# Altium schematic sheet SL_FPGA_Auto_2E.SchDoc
size C; Generated From FPGA Project: SpiritLevel.PRJFPG; UNUSED_SPECIAL: RouteSeparate; UNUSED_IO: Ignore; VREF: Ignore; UNUSED_INPUT: Ignore; DocumentNumber: 1; SheetNumber: 1; SheetTotal: 5; Library Name: SpiritLevel_2E.SchLib
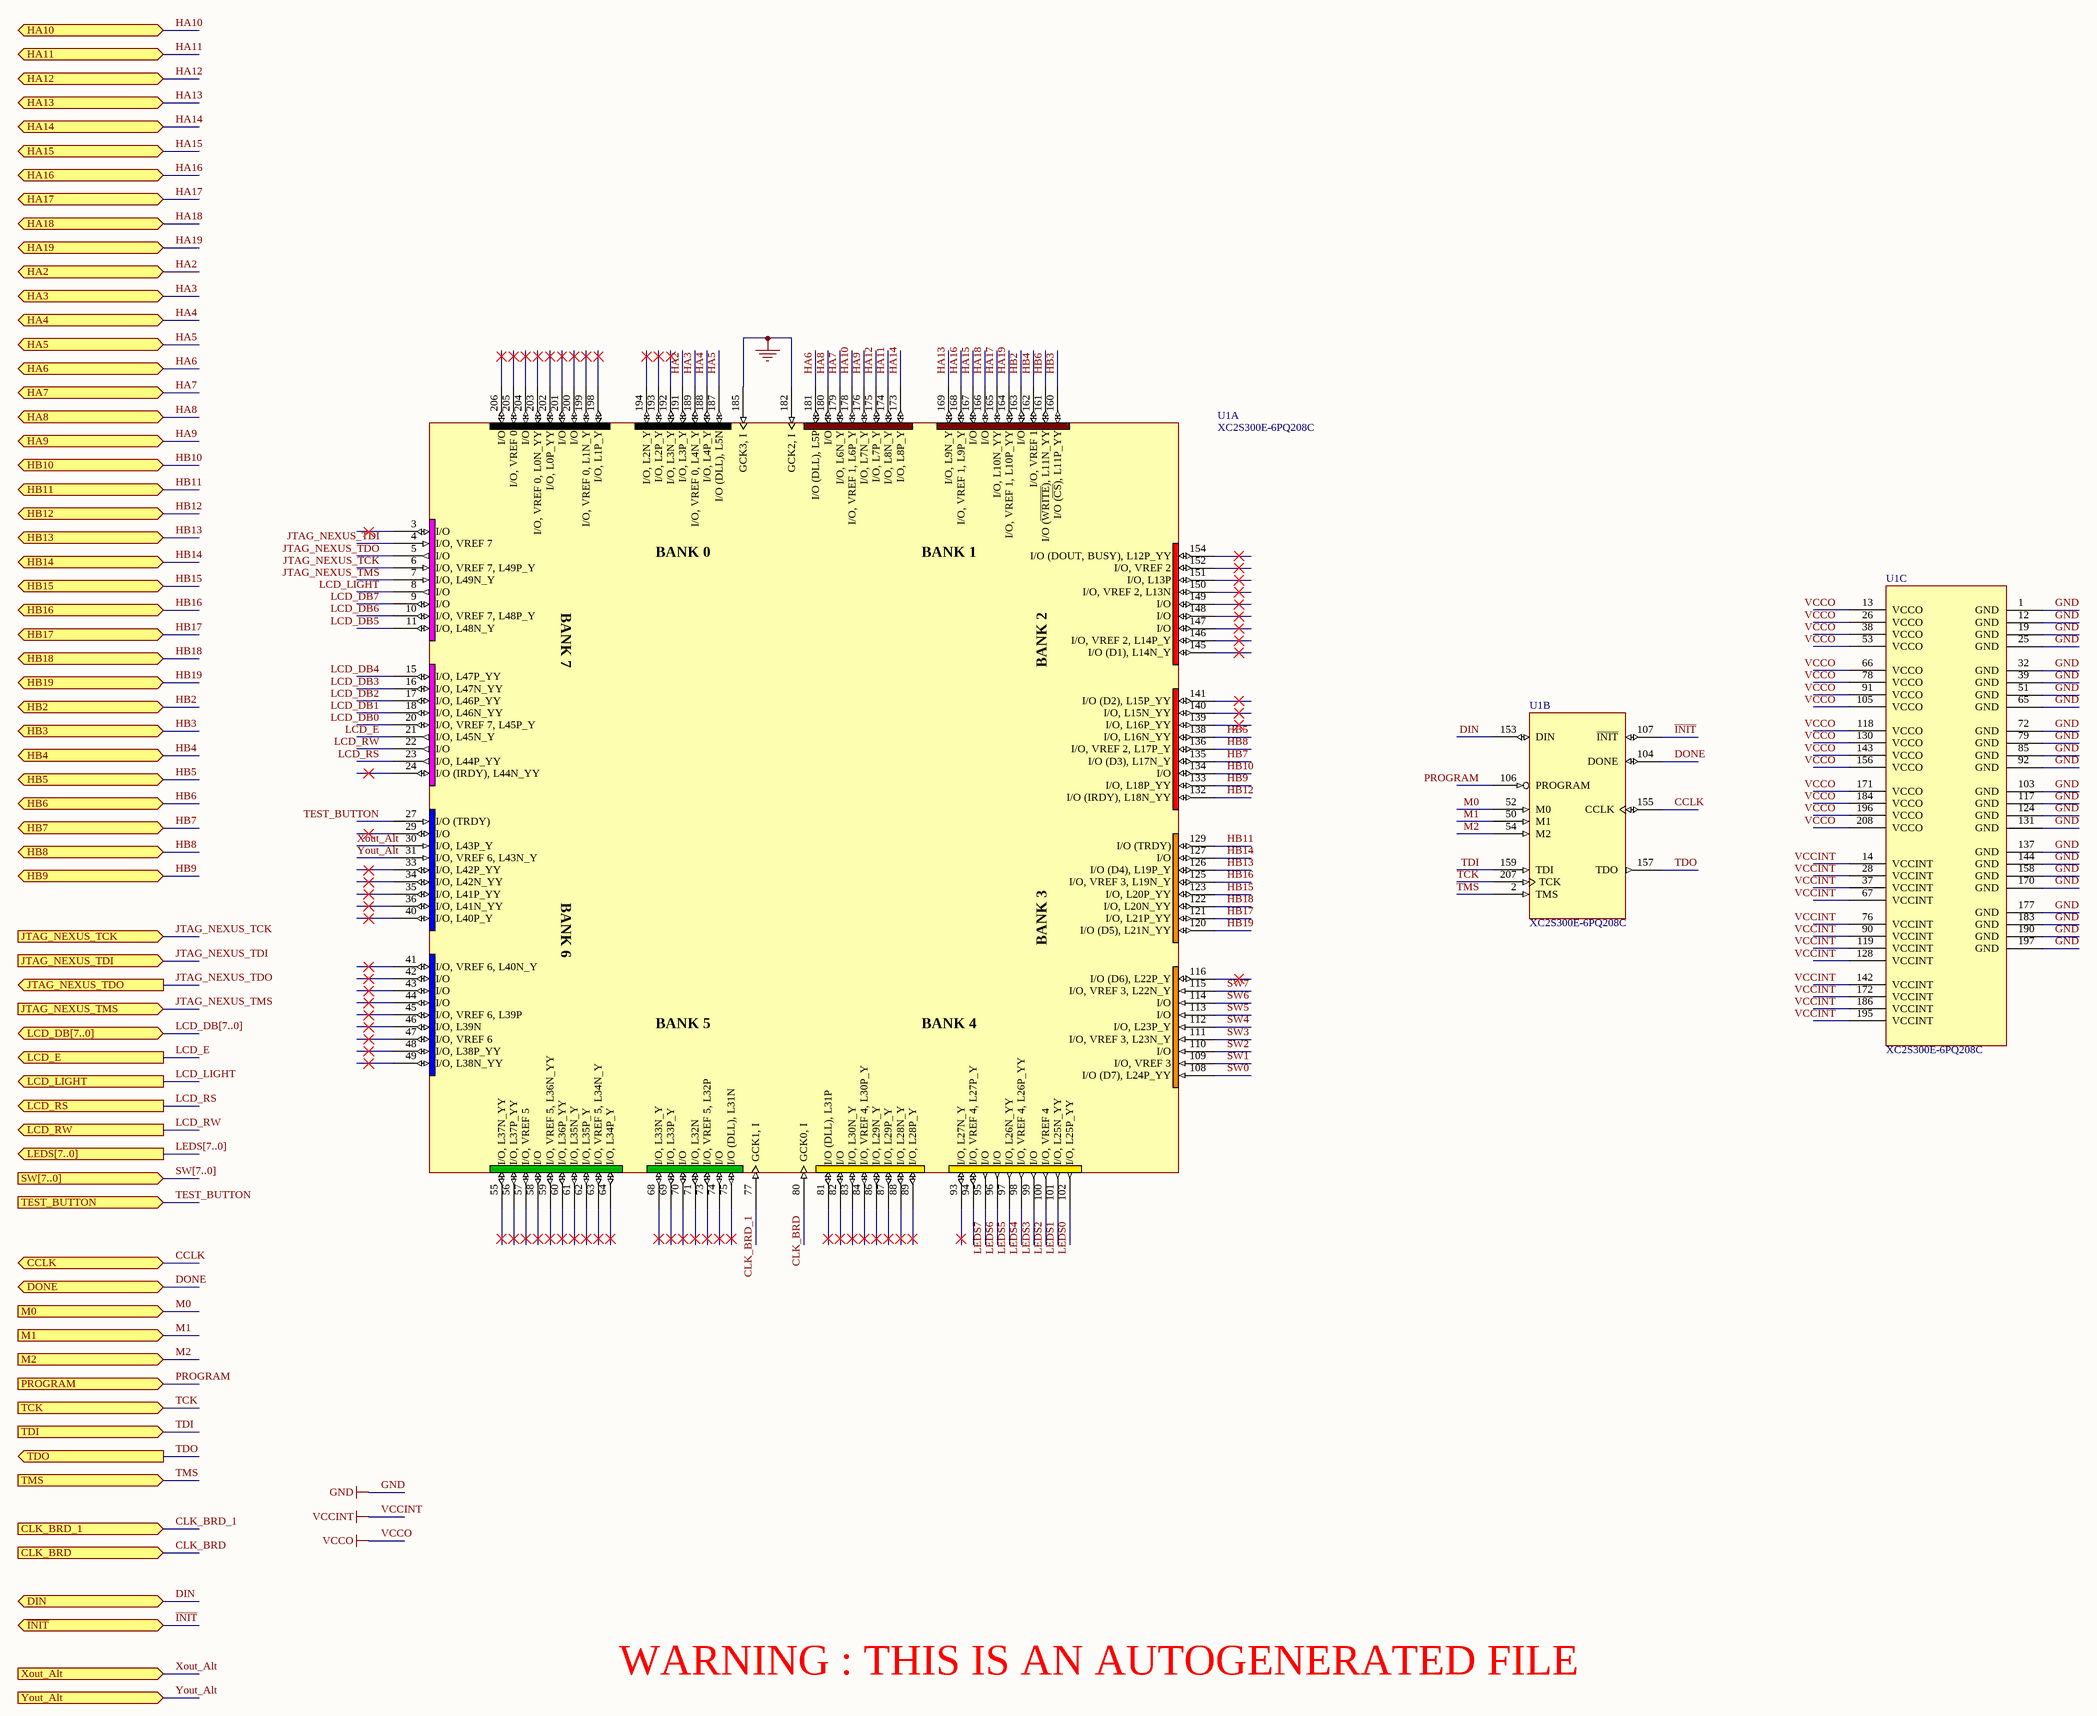
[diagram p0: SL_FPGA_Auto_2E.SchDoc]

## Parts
U1  XC2S300E-6PQ208C  [PQ208]  (parts A,B,C of 3)

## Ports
CCLK (bidir), CLK_BRD (in), CLK_BRD_1 (in), DIN (bidir), DONE (bidir), HA2 (bidir), HA3 (bidir), HA4 (bidir), HA5 (bidir), HA6 (bidir), HA7 (bidir), HA8 (bidir), HA9 (bidir), HA10 (bidir), HA11 (bidir), HA12 (bidir), HA13 (bidir), HA14 (bidir), HA15 (bidir), HA16 (bidir), HA17 (bidir), HA18 (bidir), HA19 (bidir), HB2 (bidir), HB3 (bidir), HB4 (bidir), HB5 (bidir), HB6 (bidir), HB7 (bidir), HB8 (bidir), HB9 (bidir), HB10 (bidir), HB11 (bidir), HB12 (bidir), HB13 (bidir), HB14 (bidir), HB15 (bidir), HB16 (bidir), HB17 (bidir), HB18 (bidir), HB19 (bidir), JTAG_NEXUS_TCK (in), JTAG_NEXUS_TDI (in), JTAG_NEXUS_TDO (out), JTAG_NEXUS_TMS (in), LCD_DB[7..0] (bidir), LCD_E (out), LCD_LIGHT (out), LCD_RS (out), LCD_RW (out), LEDS[7..0] (out), M0 (in), M1 (in), M2 (in), PROGRAM (in), SW[7..0] (in), TCK (in), TDI (in), TDO (out), TEST_BUTTON (in), TMS (in), Xout_Alt (in), Yout_Alt (in), ~{INIT} (bidir)

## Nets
GND: U1.1(GND) U1.12(GND) U1.19(GND) U1.25(GND) U1.32(GND) U1.39(GND) U1.51(GND) U1.65(GND) U1.72(GND) U1.79(GND) U1.85(GND) U1.92(GND) U1.103(GND) U1.117(GND) U1.124(GND) U1.131(GND) U1.137(GND) U1.144(GND) U1.158(GND) U1.170(GND) U1.177(GND) U1.182(GCK2,_I) U1.183(GND) U1.185(GCK3,_I) U1.190(GND) U1.197(GND)
VCCINT: U1.14(VCCINT) U1.28(VCCINT) U1.37(VCCINT) U1.67(VCCINT) U1.76(VCCINT) U1.90(VCCINT) U1.119(VCCINT) U1.128(VCCINT) U1.142(VCCINT) U1.172(VCCINT) U1.186(VCCINT) U1.195(VCCINT)
VCCO: U1.13(VCCO) U1.26(VCCO) U1.38(VCCO) U1.53(VCCO) U1.66(VCCO) U1.78(VCCO) U1.91(VCCO) U1.105(VCCO) U1.118(VCCO) U1.130(VCCO) U1.143(VCCO) U1.156(VCCO) U1.171(VCCO) U1.184(VCCO) U1.196(VCCO) U1.208(VCCO)
CCLK: U1.155(CCLK) ; port CCLK
CLK_BRD: U1.80(GCK0,_I) ; port CLK_BRD
CLK_BRD_1: U1.77(GCK1,_I) ; port CLK_BRD_1
DIN: U1.153(DIN) ; port DIN
DONE: U1.104(DONE) ; port DONE
HA2: U1.191(I/O,_L3P_Y) ; port HA2
HA3: U1.189(I/O,_VREF_0,_L4N_Y) ; port HA3
HA4: U1.188(I/O,_L4P_Y) ; port HA4
HA5: U1.187(I/O_(DLL),_L5N) ; port HA5
HA6: U1.181(I/O_(DLL),_L5P) ; port HA6
HA7: U1.179(I/O,_L6N_Y) ; port HA7
HA8: U1.180(I/O) ; port HA8
HA9: U1.176(I/O,_L7N_Y) ; port HA9
HA10: U1.178(I/O,_VREF_1,_L6P_Y) ; port HA10
HA11: U1.174(I/O,_L8N_Y) ; port HA11
HA12: U1.175(I/O,_L7P_Y) ; port HA12
HA13: U1.169(I/O,_L9N_Y) ; port HA13
HA14: U1.173(I/O,_L8P_Y) ; port HA14
HA15: U1.167(I/O) ; port HA15
HA16: U1.168(I/O,_VREF_1,_L9P_Y) ; port HA16
HA17: U1.165(I/O,_L10N_YY) ; port HA17
HA18: U1.166(I/O) ; port HA18
HA19: U1.164(I/O,_VREF_1,_L10P_YY) ; port HA19
HB2: U1.163(I/O) ; port HB2
HB3: U1.160(I/O_(~{CS}),_L11P_YY) ; port HB3
HB4: U1.162(I/O,_VREF_1) ; port HB4
HB5: U1.138(I/O,_L16N_YY) ; port HB5
HB6: U1.161(I/O_(~{WRITE}),_L11N_YY) ; port HB6
HB7: U1.135(I/O_(D3),_L17N_Y) ; port HB7
HB8: U1.136(I/O,_VREF_2,_L17P_Y) ; port HB8
HB9: U1.133(I/O,_L18P_YY) ; port HB9
HB10: U1.134(I/O) ; port HB10
HB11: U1.129(I/O_(TRDY)) ; port HB11
HB12: U1.132(I/O_(IRDY),_L18N_YY) ; port HB12
HB13: U1.126(I/O_(D4),_L19P_Y) ; port HB13
HB14: U1.127(I/O) ; port HB14
HB15: U1.123(I/O,_L20P_YY) ; port HB15
HB16: U1.125(I/O,_VREF_3,_L19N_Y) ; port HB16
HB17: U1.121(I/O,_L21P_YY) ; port HB17
HB18: U1.122(I/O,_L20N_YY) ; port HB18
HB19: U1.120(I/O_(D5),_L21N_YY) ; port HB19
~{INIT}: U1.107(~{INIT}) ; port ~{INIT}
JTAG_NEXUS_TCK: U1.6(I/O,_VREF_7,_L49P_Y) ; port JTAG_NEXUS_TCK
JTAG_NEXUS_TDI: U1.4(I/O,_VREF_7) ; port JTAG_NEXUS_TDI
JTAG_NEXUS_TDO: U1.5(I/O) ; port JTAG_NEXUS_TDO
JTAG_NEXUS_TMS: U1.7(I/O,_L49N_Y) ; port JTAG_NEXUS_TMS
LCD_DB0: U1.20(I/O,_VREF_7,_L45P_Y)
LCD_DB1: U1.18(I/O,_L46N_YY)
LCD_DB2: U1.17(I/O,_L46P_YY)
LCD_DB3: U1.16(I/O,_L47N_YY)
LCD_DB4: U1.15(I/O,_L47P_YY)
LCD_DB5: U1.11(I/O,_L48N_Y)
LCD_DB6: U1.10(I/O,_VREF_7,_L48P_Y)
LCD_DB7: U1.9(I/O)
LCD_E: U1.21(I/O,_L45N_Y) ; port LCD_E
LCD_LIGHT: U1.8(I/O) ; port LCD_LIGHT
LCD_RS: U1.23(I/O,_L44P_YY) ; port LCD_RS
LCD_RW: U1.22(I/O) ; port LCD_RW
LEDS0: U1.102(I/O,_L25P_YY)
LEDS1: U1.101(I/O,_L25N_YY)
LEDS2: U1.100(I/O,_VREF_4)
LEDS3: U1.99(I/O)
LEDS4: U1.98(I/O,_VREF_4,_L26P_YY)
LEDS5: U1.97(I/O,_L26N_YY)
LEDS6: U1.96(I/O)
LEDS7: U1.95(I/O)
M0: U1.52(M0) ; port M0
M1: U1.50(M1) ; port M1
M2: U1.54(M2) ; port M2
PROGRAM: U1.106(PROGRAM) ; port PROGRAM
SW0: U1.108(I/O_(D7),_L24P_YY)
SW1: U1.109(I/O,_VREF_3)
SW2: U1.110(I/O)
SW3: U1.111(I/O,_VREF_3,_L23N_Y)
SW4: U1.112(I/O,_L23P_Y)
SW5: U1.113(I/O)
SW6: U1.114(I/O)
SW7: U1.115(I/O,_VREF_3,_L22N_Y)
TCK: U1.207(TCK) ; port TCK
TDI: U1.159(TDI) ; port TDI
TDO: U1.157(TDO) ; port TDO
TEST_BUTTON: U1.27(I/O_(TRDY)) ; port TEST_BUTTON
TMS: U1.2(TMS) ; port TMS
Xout_Alt: U1.30(I/O,_L43P_Y) ; port Xout_Alt
Yout_Alt: U1.31(I/O,_VREF_6,_L43N_Y) ; port Yout_Alt

Not connected (* = marked no-connect by the designer): U1 3(I/O)* 24(I/O_(IRDY),_L44N_YY)* 29(I/O)* 33(I/O,_L42P_YY)* 34(I/O,_L42N_YY)* 35(I/O,_L41P_YY)* 36(I/O,_L41N_YY)* 40(I/O,_L40P_Y)* 41(I/O,_VREF_6,_L40N_Y)* 42(I/O)* 43(I/O)* 44(I/O)* 45(I/O,_VREF_6,_L39P)* 46(I/O,_L39N)* 47(I/O,_VREF_6)* 48(I/O,_L38P_YY)* 49(I/O,_L38N_YY)* 55(I/O,_L37N_YY)* 56(I/O,_L37P_YY)* 57(I/O,_VREF_5)* 58(I/O)* 59(I/O,_VREF_5,_L36N_YY)* 60(I/O,_L36P_YY)* 61(I/O,_L35N_Y)* 62(I/O,_L35P_Y)* 63(I/O,_VREF_5,_L34N_Y)* 64(I/O,_L34P_Y)* 68(I/O,_L33N_Y)* 69(I/O,_L33P_Y)* 70(I/O)* 71(I/O,_L32N)* 73(I/O,_VREF_5,_L32P)* 74(I/O)* 75(I/O_(DLL),_L31N)* 81(I/O_(DLL),_L31P)* 82(I/O)* 83(I/O,_L30N_Y)* 84(I/O,_VREF_4,_L30P_Y)* 86(I/O,_L29N_Y)* 87(I/O,_L29P_Y)* 88(I/O,_L28N_Y)* 89(I/O,_L28P_Y)* 93(I/O,_L27N_Y)* 94(I/O,_VREF_4,_L27P_Y) 116(I/O_(D6),_L22P_Y)* 139(I/O,_L16P_YY)* 140(I/O,_L15N_YY)* 141(I/O_(D2),_L15P_YY)* 145(I/O_(D1),_L14N_Y)* 146(I/O,_VREF_2,_L14P_Y)* 147(I/O)* 148(I/O)* 149(I/O)* 150(I/O,_VREF_2,_L13N)* 151(I/O,_L13P)* 152(I/O,_VREF_2)* 154(I/O_(DOUT,_BUSY),_L12P_YY)* 192(I/O,_L3N_Y)* 193(I/O,_L2P_Y)* 194(I/O,_L2N_Y)* 198(I/O,_L1P_Y)* 199(I/O,_VREF_0,_L1N_Y)* 200(I/O)* 201(I/O)* 202(I/O,_L0P_YY)* 203(I/O,_VREF_0,_L0N_YY)* 204(I/O)* 205(I/O,_VREF_0)* 206(I/O)*

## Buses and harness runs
bus LCD_DB[7..0] = port LCD_DB[7..0]
bus LEDS[7..0] = port LEDS[7..0]
bus SW[7..0] = port SW[7..0]

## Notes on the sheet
- WARNING : THIS IS AN AUTOGENERATED FILE

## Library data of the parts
U1 = XC2S300E-6PQ208C: Spartan-IIE 1.8V FPGA, 208-Pin PQFP, Standard Performance, Commercial Grade; Package Information: Latest Revision: ver1.1, Oct-2002; Code - JEDEC: MS-029-FA-1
